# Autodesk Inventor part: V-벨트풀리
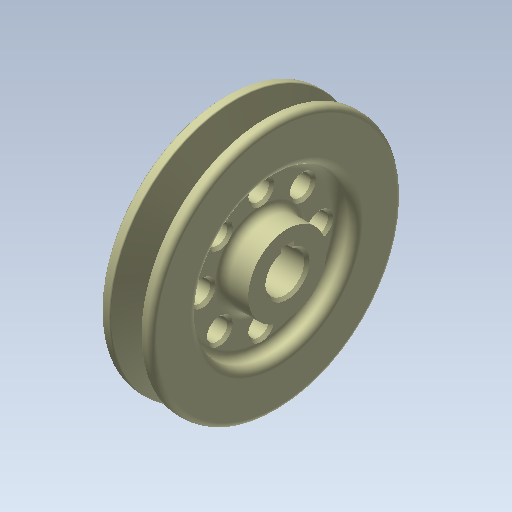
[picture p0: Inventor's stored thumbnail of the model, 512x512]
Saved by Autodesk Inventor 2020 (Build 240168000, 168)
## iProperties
Created: 2011-02
Part Number: V-벨트풀리
Document SubType Name: Modeling
Designer: pww
Density: 1 g/cm^3
Material: 알루미늄 6061
Appearance: 기본값(1)
Author: pww
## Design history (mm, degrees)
sketch "스케치1"
  geometry: L1 (0, 0)-(24, 0); L2 (0, 7.5)-(24, 7.5); L3 (24, 7.5)-(24, 15); L4 (24, 15)-(14, 15); L5 (14, 15)-(14, 30); L6 (14, 30)-(20, 30); L7 (20, 30)-(20, 48); L8 (20, 48)-(15.976, 48); L9 (15.976, 48)-(12.154, 35.5); L10 (12.154, 35.5)-(7.846, 35.5); L11 (7.846, 35.5)-(4.024, 48); L12 (4.024, 48)-(0, 48); L13 (0, 48)-(0, 30); L14 (0, 30)-(6, 30); L15 (6, 30)-(6, 15); L16 (6, 15)-(0, 15); L17 (0, 15)-(0, 7.5); 2 further points
  constraints: 34 end point, 13 parallel, 4 equal length, 3 collinear, 2 point on line, 2 vertical alignment, 1 horizontal, 1 horizontal alignment, 1 perpendicular
  dimensions: "d0" = 24 distance of L1.start L1.end; "d1" = 34 deg angle of L9 L11; "d2" = 9.2 distance of point (14.6, 43.5) point (5.4, 43.5); "d3" = 4.5 distance from line of point (5.4, 43.5) L12; "d4" = 8 distance from line of L10 point (5.4, 43.5); "d5" = 8 distance between parallel lines of L5 L15; "d6" = 6 distance of L13.end L14.end; "d7" = 15 diameter of L2 L1; "d8" = 30 diameter of L4 L1; "d9" = 60 diameter of L6 L1; "d10" = 96 diameter of L8 L1
revolve "회전1" sketch "스케치1" stored, may be unused: angle "d11" = 90 deg
fillet "모깎기1" dims "d12" = 2, "d13" = 1, "d14" = 0.5, "d15" = 3
sketch "스케치2"
  geometry: L1 (-2.5, 7.071)-(2.5, 7.071); L2 (2.5, 7.071)-(2.5, 9.8); L3 (2.5, 9.8)-(-2.5, 9.8); L4 (-2.5, 9.8)-(-2.5, 7.071); A1 r 7.5 centre (0, 0) between (-2.5, 7.071) and (2.5, 7.071) reference; 1 further point
  constraints: 8 end point, 2 parallel, 2 point on circle, 1 horizontal, 1 perpendicular
  dimensions: "d16" = 17.3 dimension on A1 L3; "d17" = 5 distance of L2.end L3.end
extrude "돌출1" cut sketch "스케치2" extent not by distance; stored distance "d18" = 10; taper "d19" = 0 deg
sketch "스케치3"
  geometry: 4 further points
  constraints: 2 horizontal alignment, 1 vertical alignment, 1 other
  dimensions: "d20" = 22.5 distance of point (0, 22.5) point (0, 0)
hole "구멍1" sketch "스케치3" at (0, 22.5) diameter "d22" = 8; stored, may be unused: countersink angle "d26" = 90 deg, drill point angle "d28" = 118 deg; dims "d23" = 6, "d24" = 4, "d25" = 2, "d27" = 8
chamfer "모따기1" distance "d33" = 1; stored, may be unused: second distance "d34" = 2, angle "d35" = 45 deg
node "솔리드1"
pattern_circular "원형 패턴1" dims angle "d31" = 360 deg
